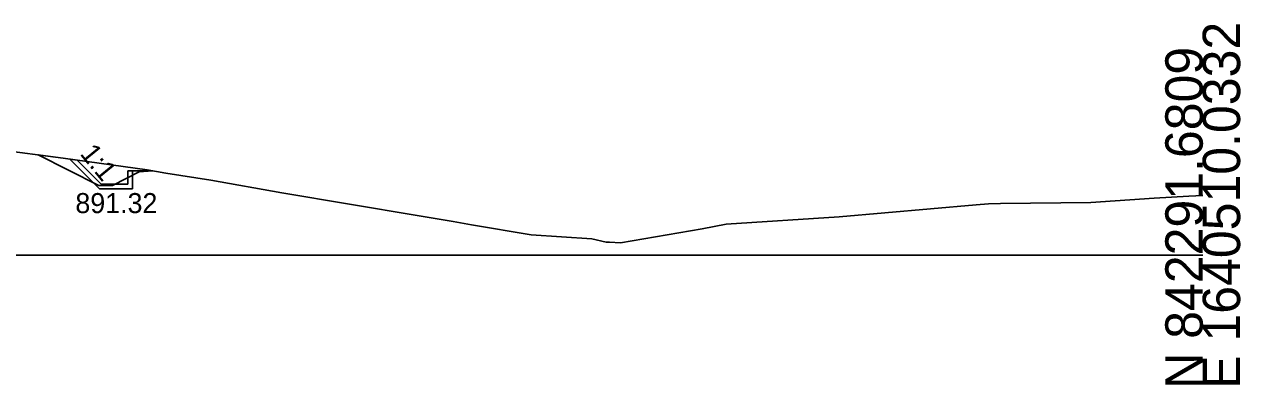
# Model space of a CAD drawing. Extents: x -26 to 1640245, y -10 to 842531.
# Drawn here: x 211.8 to 302.8, y 490.3 to 517.3 of the extents above; entities that cross this region are included whole.
import ezdxf

# ---------------------------------------------------------------- set-up
doc = ezdxf.new("R2010")
doc.units = 0
for name, color, linetype in [('Exist Cross Section Cell', 7, 'Continuous'), ('Exist XS Ground Line', 7, 'Continuous'), ('Prop CMT Concrete Ditch', 7, 'Continuous'), ('Prop XS Ditch Standard Text', 7, 'Continuous'), ('Prop XS Side Slope Text', 7, 'Continuous'), ('Scratch_Level_0', 7, 'Continuous'), ('Scratch_Level_2', 7, 'Continuous')]:
    doc.layers.add(name, color=color, linetype=linetype)

msp = doc.modelspace()

# ---------------------------------------------------------------- linework, layer by layer
at = {"layer": 'Exist Cross Section Cell'}
msp.add_line((150, 500), (300, 500), dxfattribs=at)
at = {"layer": 'Exist XS Ground Line'}
for p, q in [((208.366, 508.09), (214.73, 507.273)), ((214.73, 507.273), (221.005, 506.391)), ((221.005, 506.391), (222.406, 506.136)), ((222.406, 506.136), (225.757, 505.62)), ((225.757, 505.62), (231.084, 504.687)), ((231.084, 504.687), (241.203, 502.981)), ((296.376, 504.274), (298.953, 504.432)), ((298.953, 504.432), (300, 504.476)), ((272.789, 502.88), (283.04, 503.775)), ((283.04, 503.775), (283.969, 503.847)), ((283.969, 503.847), (284.86, 503.878)), ((284.86, 503.878), (291.622, 503.94)), ((291.622, 503.94), (296.376, 504.274)), ((241.203, 502.981), (243.908, 502.524)), ((243.908, 502.524), (245.277, 502.291)), ((264.331, 502.332), (272.789, 502.88)), ((245.277, 502.291), (249.739, 501.538)), ((256.438, 500.941), (262.533, 501.972)), ((262.533, 501.972), (264.331, 502.332)), ((249.739, 501.538), (254.274, 501.218)), ((254.274, 501.218), (255.359, 500.985)), ((255.359, 500.985), (255.597, 500.975)), ((255.597, 500.975), (256.438, 500.941))]:
    msp.add_line(p, q, dxfattribs=at)
at = {"layer": 'Prop CMT Concrete Ditch'}
for p, q in [((217.429, 504.986), (215.21, 507.206)), ((215.21, 507.206), (215.757, 507.129)), ((219.567, 506.319), (219.567, 505.319)), ((219.567, 506.319), (219.9, 506.319)), ((219.9, 506.319), (221.4, 506.319)), ((219.9, 506.319), (221.4, 506.319)), ((219.9, 506.319), (219.9, 504.986)), ((219.567, 505.319), (217.567, 505.319)), ((219.9, 504.986), (217.429, 504.986))]:
    msp.add_line(p, q, dxfattribs=at)
msp.add_lwpolyline([(217.567, 505.319), (216.567, 506.319), (215.757, 507.129)], dxfattribs=at)
at = {"layer": 'Scratch_Level_2'}
for p, q in [((212.841, 507.516), (217.4, 505.236)), ((218.4, 505.236), (220.4, 506.236)), ((220.4, 506.236), (221.4, 506.319)), ((221.4, 506.319), (221.005, 506.391)), ((217.4, 505.236), (218.4, 505.236))]:
    msp.add_line(p, q, dxfattribs=at)
msp.add_lwpolyline([(221.005, 506.391), (214.73, 507.273), (212.841, 507.516)], dxfattribs=at)

# ---------------------------------------------------------------- texts
at = {"layer": 'Exist Cross Section Cell'}
for s, p in [('E 1640510.0332', (302.8, 490)), ('N 842291.6809', (300, 490))]:
    msp.add_text(s, height=2.8, rotation=90, dxfattribs=at).set_placement(p)
at = {"layer": 'Prop XS Ditch Standard Text'}
msp.add_text('891.32', height=1.5, dxfattribs=at).set_placement((215.633, 503.157))
at = {"layer": 'Prop XS Side Slope Text'}
msp.add_text('1:1', height=1.5, rotation=309.22034, dxfattribs=at).set_placement((215.92, 507.583))
at = {"layer": 'Scratch_Level_0'}
for s, p in [('Exterior Boundary', (222.215, 506.156)), ('RT_Slope_Fill', (222.231, 506.156)), ('Exterior Boundary', (222.284, 506.144)), ('RT_Slope_Fill', (222.3, 506.144))]:
    msp.add_text(s, height=0.01, dxfattribs=at).set_placement(p)

doc.saveas('drawing.dxf')
